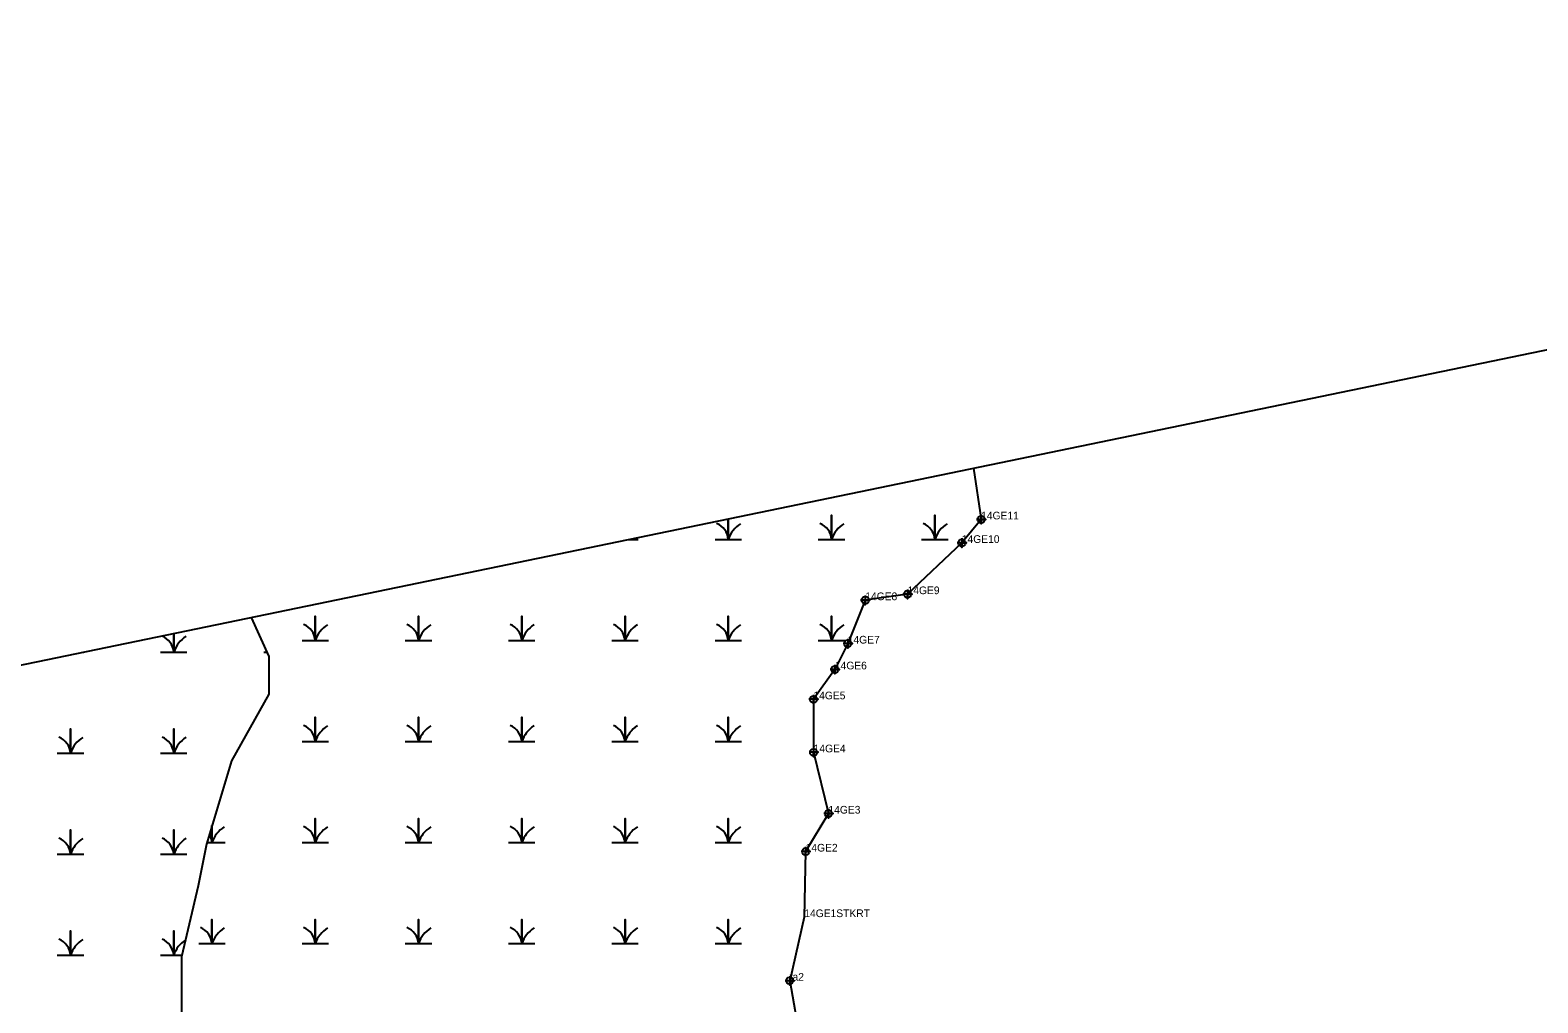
# Model space of a CAD drawing. Extents: x 2071991 to 2268989, y 436479 to 469629.
# Drawn here: x 2259977 to 2260958, y 442009 to 442642 of the extents above; entities that cross this region are included whole.
import ezdxf

# ---------------------------------------------------------------- set-up
doc = ezdxf.new("R2010")
doc.units = 0
for name, color, linetype in [('approx_PSA', 7, 'Continuous'), ('Exist Environmental Wetland Boundary', 7, 'Continuous'), ('Exist Environmental Wetland Boundary Cogo Comment', 7, 'Continuous'), ('Exist Environmental Wetland Boundary Cogo Point CELL', 7, 'Continuous'), ('Exist Hydro Jurisdictional Stream or Body of Water NEU Mitigable', 7, 'Continuous'), ('Exist Hydro Swamp or Marsh', 7, 'Continuous')]:
    doc.layers.add(name, color=color, linetype=linetype)

msp = doc.modelspace()

# ---------------------------------------------------------------- linework, layer by layer
at = {"layer": 'approx_PSA'}
msp.add_line((2259436.93, 442118.42), (2261971.8, 442641.95), dxfattribs=at)
at = {"layer": 'Exist Environmental Wetland Boundary'}
for points in [[(2260590.87, 442356.74), (2260595.94, 442323.44), (2260583.37, 442308.11), (2260548.06, 442274.76), (2260520.53, 442270.84), (2260509.12, 442242.61), (2260500.74, 442225.79), (2260486.8, 442206.3), (2260486.92, 442171.79), (2260496.57, 442131.91), (2260481.73, 442107.18), (2260480.85, 442064.51)], [(2260480.85, 442064.51), (2260471.33, 442023.13), (2260478.24, 441984.37), (2260453.18, 441919.62), (2260429.42, 441892.42), (2260405.4, 441828.34), (2260382.58, 441774.65), (2260378.54, 441677.46), (2260371.11, 441593.52), (2260413.53, 441501.55), (2260451.72, 441470.49), (2260474.35, 441433.89), (2260474.01, 441354.15), (2260435.58, 441283.64), (2260458.13, 441223.04), (2260478.69, 441159.57), (2260523.25, 441103.96), (2260546.39, 441048.63)]]:
    msp.add_lwpolyline(points, dxfattribs=at)
at = {"layer": 'Exist Environmental Wetland Boundary Cogo Point CELL'}
for points in [[(2260595.94, 442326.44), (2260595.94, 442320.44), (2260595.94, 442323.44), (2260598.94, 442323.44), (2260592.94, 442323.44)], [(2260583.37, 442311.11), (2260583.37, 442305.11), (2260583.37, 442308.11), (2260586.37, 442308.11), (2260580.37, 442308.11)], [(2260520.53, 442273.84), (2260520.53, 442267.84), (2260520.53, 442270.84), (2260523.53, 442270.84), (2260517.53, 442270.84)], [(2260548.06, 442277.76), (2260548.06, 442271.76), (2260548.06, 442274.76), (2260551.06, 442274.76), (2260545.06, 442274.76)], [(2260509.12, 442245.61), (2260509.12, 442239.61), (2260509.12, 442242.61), (2260512.12, 442242.61), (2260506.12, 442242.61)], [(2260500.74, 442228.79), (2260500.74, 442222.79), (2260500.74, 442225.79), (2260503.74, 442225.79), (2260497.74, 442225.79)], [(2260486.8, 442209.3), (2260486.8, 442203.3), (2260486.8, 442206.3), (2260489.8, 442206.3), (2260483.8, 442206.3)], [(2260486.92, 442174.79), (2260486.92, 442168.79), (2260486.92, 442171.79), (2260489.92, 442171.79), (2260483.92, 442171.79)], [(2260496.57, 442134.91), (2260496.57, 442128.91), (2260496.57, 442131.91), (2260499.57, 442131.91), (2260493.57, 442131.91)], [(2260481.73, 442110.18), (2260481.73, 442104.18), (2260481.73, 442107.18), (2260484.73, 442107.18), (2260478.73, 442107.18)], [(2260471.33, 442026.13), (2260471.33, 442020.13), (2260471.33, 442023.13), (2260474.33, 442023.13), (2260468.33, 442023.13)]]:
    msp.add_lwpolyline(points, dxfattribs=at)
for centre in [(2260595.94, 442323.44), (2260583.37, 442308.11), (2260548.06, 442274.76), (2260520.53, 442270.84), (2260509.12, 442242.61), (2260500.74, 442225.79), (2260486.8, 442206.3), (2260486.92, 442171.79), (2260496.57, 442131.91), (2260481.73, 442107.18), (2260471.33, 442023.13)]:
    msp.add_circle(centre, 2.34, dxfattribs=at)
at = {"layer": 'Exist Hydro Jurisdictional Stream or Body of Water NEU Mitigable'}
msp.add_lwpolyline([(2260120.87, 442259.67), (2260132.45, 442234.18), (2260132.45, 442209.73), (2260108.02, 442166.28), (2260091.73, 442111.96), (2260086.31, 442084.8), (2260075.45, 442038.62), (2260075.45, 442011.46), (2260075.45, 441973.44), (2260075.45, 441954.42)], dxfattribs=at)
at = {"layer": 'Exist Hydro Swamp or Marsh'}
for p, q in [((2260366.35, 442310.37), (2260372.78, 442310.37)), ((2260011.27, 442237.04), (2260011.88, 442237.04)), ((2260129.08, 442237.04), (2260131.15, 442237.04))]:
    msp.add_line(p, q, dxfattribs=at)
for points in [[(2260422.78, 442310.37), (2260431.38, 442310.37), (2260431.38, 442323.8)], [(2260431.38, 442323.8), (2260431.38, 442310.37), (2260439.98, 442310.37)], [(2260489.98, 442310.37), (2260498.58, 442310.37), (2260498.58, 442326.15), (2260498.58, 442310.37), (2260507.18, 442310.37)], [(2260557.18, 442310.37), (2260565.79, 442310.37), (2260565.79, 442326.15), (2260565.79, 442310.37), (2260574.39, 442310.37)], [(2260153.96, 442244.59), (2260162.57, 442244.59), (2260162.57, 442260.37), (2260162.57, 442244.59), (2260171.17, 442244.59)], [(2260221.17, 442244.59), (2260229.77, 442244.59), (2260229.77, 442260.37), (2260229.77, 442244.59), (2260238.37, 442244.59)], [(2260288.37, 442244.59), (2260296.97, 442244.59), (2260296.97, 442260.37), (2260296.97, 442244.59), (2260305.57, 442244.59)], [(2260355.57, 442244.59), (2260364.18, 442244.59), (2260364.18, 442260.37), (2260364.18, 442244.59), (2260372.78, 442244.59)], [(2260422.78, 442244.59), (2260431.38, 442244.59), (2260431.38, 442260.37), (2260431.38, 442244.59), (2260439.98, 442244.59)], [(2260489.98, 442244.59), (2260498.58, 442244.59), (2260498.58, 442260.37), (2260498.58, 442244.59), (2260507.18, 442244.59)], [(2260061.88, 442237.04), (2260070.48, 442237.04), (2260070.48, 442249.27)], [(2260070.48, 442249.27), (2260070.48, 442237.04), (2260079.08, 442237.04)], [(2259994.68, 442171.26), (2260003.28, 442171.26), (2260003.28, 442187.04), (2260003.28, 442171.26), (2260011.88, 442171.26)], [(2260061.88, 442171.26), (2260070.48, 442171.26), (2260070.48, 442187.04), (2260070.48, 442171.26), (2260079.08, 442171.26)], [(2260153.96, 442178.81), (2260162.57, 442178.81), (2260162.57, 442194.59), (2260162.57, 442178.81), (2260171.17, 442178.81)], [(2260221.17, 442178.81), (2260229.77, 442178.81), (2260229.77, 442194.59), (2260229.77, 442178.81), (2260238.37, 442178.81)], [(2260288.37, 442178.81), (2260296.97, 442178.81), (2260296.97, 442194.59), (2260296.97, 442178.81), (2260305.57, 442178.81)], [(2260355.57, 442178.81), (2260364.18, 442178.81), (2260364.18, 442194.59), (2260364.18, 442178.81), (2260372.78, 442178.81)], [(2260422.78, 442178.81), (2260431.38, 442178.81), (2260431.38, 442194.59), (2260431.38, 442178.81), (2260439.98, 442178.81)], [(2260153.96, 442113.03), (2260162.57, 442113.03), (2260162.57, 442128.81), (2260162.57, 442113.03), (2260171.17, 442113.03)], [(2260221.17, 442113.03), (2260229.77, 442113.03), (2260229.77, 442128.81), (2260229.77, 442113.03), (2260238.37, 442113.03)], [(2260288.37, 442113.03), (2260296.97, 442113.03), (2260296.97, 442128.81), (2260296.97, 442113.03), (2260305.57, 442113.03)], [(2260355.57, 442113.03), (2260364.18, 442113.03), (2260364.18, 442128.81), (2260364.18, 442113.03), (2260372.78, 442113.03)], [(2260422.78, 442113.03), (2260431.38, 442113.03), (2260431.38, 442128.81), (2260431.38, 442113.03), (2260439.98, 442113.03)], [(2259994.68, 442105.48), (2260003.28, 442105.48), (2260003.28, 442121.26), (2260003.28, 442105.48), (2260011.88, 442105.48)], [(2260061.88, 442105.48), (2260070.48, 442105.48), (2260070.48, 442121.26), (2260070.48, 442105.48), (2260079.08, 442105.48)], [(2260092.06, 442113.03), (2260095.36, 442113.03), (2260095.36, 442124.06)], [(2260095.36, 442124.06), (2260095.36, 442113.03), (2260103.96, 442113.03)], [(2260086.76, 442047.25), (2260095.36, 442047.25), (2260095.36, 442063.03), (2260095.36, 442047.25), (2260103.96, 442047.25)], [(2260153.96, 442047.25), (2260162.57, 442047.25), (2260162.57, 442063.03), (2260162.57, 442047.25), (2260171.17, 442047.25)], [(2260221.17, 442047.25), (2260229.77, 442047.25), (2260229.77, 442063.03), (2260229.77, 442047.25), (2260238.37, 442047.25)], [(2260288.37, 442047.25), (2260296.97, 442047.25), (2260296.97, 442063.03), (2260296.97, 442047.25), (2260305.57, 442047.25)], [(2260355.57, 442047.25), (2260364.18, 442047.25), (2260364.18, 442063.03), (2260364.18, 442047.25), (2260372.78, 442047.25)], [(2260422.78, 442047.25), (2260431.38, 442047.25), (2260431.38, 442063.03), (2260431.38, 442047.25), (2260439.98, 442047.25)], [(2259994.68, 442039.69), (2260003.28, 442039.69), (2260003.28, 442055.48), (2260003.28, 442039.69), (2260011.88, 442039.69)], [(2260061.88, 442039.69), (2260070.48, 442039.69), (2260070.48, 442055.48), (2260070.48, 442039.69), (2260075.7, 442039.69)]]:
    msp.add_lwpolyline(points, dxfattribs=at)
for centre, radius, start, end in [((2260419.11, 442309.49), 12.3, 4.14034, 67.53497), ((2260449.62, 442304.31), 19.22, 122.12745, 161.62219), ((2260486.32, 442309.49), 12.3, 4.14034, 67.53497), ((2260516.82, 442304.31), 19.22, 122.12745, 161.62219), ((2260553.52, 442309.49), 12.3, 4.14034, 67.53497), ((2260584.03, 442304.31), 19.22, 122.12745, 161.62219), ((2260150.3, 442243.7), 12.3, 4.14034, 67.53497), ((2260180.81, 442238.53), 19.22, 122.12745, 161.62219), ((2260217.5, 442243.7), 12.3, 4.14034, 67.53497), ((2260248.01, 442238.53), 19.22, 122.12745, 161.62219), ((2260284.71, 442243.7), 12.3, 4.14034, 67.53497), ((2260315.22, 442238.53), 19.22, 122.12745, 161.62219), ((2260351.91, 442243.7), 12.3, 4.14034, 67.53497), ((2260382.42, 442238.53), 19.22, 122.12745, 161.62219), ((2260419.11, 442243.7), 12.3, 4.14034, 67.53497), ((2260449.62, 442238.53), 19.22, 122.12745, 161.62219), ((2260486.32, 442243.7), 12.3, 4.14034, 67.53497), ((2260516.82, 442238.53), 19.22, 122.12745, 161.62219), ((2260058.21, 442236.15), 12.3, 4.14034, 67.53497), ((2260088.72, 442230.98), 19.22, 122.12745, 161.62219), ((2260150.3, 442177.92), 12.3, 4.14034, 67.53497), ((2260180.81, 442172.75), 19.22, 122.12745, 161.62219), ((2260217.5, 442177.92), 12.3, 4.14034, 67.53497), ((2260248.01, 442172.75), 19.22, 122.12745, 161.62219), ((2260284.71, 442177.92), 12.3, 4.14034, 67.53497), ((2260315.22, 442172.75), 19.22, 122.12745, 161.62219), ((2260351.91, 442177.92), 12.3, 4.14034, 67.53497), ((2260382.42, 442172.75), 19.22, 122.12745, 161.62219), ((2260419.11, 442177.92), 12.3, 4.14034, 67.53497), ((2260449.62, 442172.75), 19.22, 122.12745, 161.62219), ((2259991.01, 442170.37), 12.3, 4.14034, 67.53497), ((2260021.52, 442165.2), 19.22, 122.12745, 161.62219), ((2260058.21, 442170.37), 12.3, 4.14034, 67.53497), ((2260088.72, 442165.2), 19.22, 122.12745, 161.62219), ((2260083.1, 442112.14), 12.3, 4.14034, 30.69007), ((2260113.61, 442106.97), 19.22, 122.12745, 161.62219), ((2260150.3, 442112.14), 12.3, 4.14034, 67.53497), ((2260180.81, 442106.97), 19.22, 122.12745, 161.62219), ((2260217.5, 442112.14), 12.3, 4.14034, 67.53497), ((2260248.01, 442106.97), 19.22, 122.12745, 161.62219), ((2260284.71, 442112.14), 12.3, 4.14034, 67.53497), ((2260315.22, 442106.97), 19.22, 122.12745, 161.62219), ((2260351.91, 442112.14), 12.3, 4.14034, 67.53497), ((2260382.42, 442106.97), 19.22, 122.12745, 161.62219), ((2260419.11, 442112.14), 12.3, 4.14034, 67.53497), ((2260449.62, 442106.97), 19.22, 122.12745, 161.62219), ((2260486.32, 442112.14), 12.3, 65.4791, 67.53497), ((2259991.01, 442104.59), 12.3, 4.14034, 67.53497), ((2260021.52, 442099.41), 19.22, 122.12745, 161.62219), ((2260058.21, 442104.59), 12.3, 4.14034, 67.53497), ((2260088.72, 442099.41), 19.22, 122.12745, 161.62219), ((2259991.01, 442038.81), 12.3, 4.14034, 67.53497), ((2260021.52, 442033.63), 19.22, 122.12745, 161.62219), ((2260058.21, 442038.81), 12.3, 4.14034, 67.53497), ((2260088.72, 442033.63), 19.22, 123.78408, 161.62219), ((2260083.1, 442046.36), 12.3, 4.14034, 67.53497), ((2260113.61, 442041.19), 19.22, 122.12745, 161.62219), ((2260150.3, 442046.36), 12.3, 4.14034, 67.53497), ((2260180.81, 442041.19), 19.22, 122.12745, 161.62219), ((2260217.5, 442046.36), 12.3, 4.14034, 67.53497), ((2260248.01, 442041.19), 19.22, 122.12745, 161.62219), ((2260284.71, 442046.36), 12.3, 4.14034, 67.53497), ((2260315.22, 442041.19), 19.22, 122.12745, 161.62219), ((2260351.91, 442046.36), 12.3, 4.14034, 67.53497), ((2260382.42, 442041.19), 19.22, 122.12745, 161.62219), ((2260419.11, 442046.36), 12.3, 4.14034, 67.53497), ((2260449.62, 442041.19), 19.22, 122.12745, 161.62219)]:
    msp.add_arc(centre, radius, start, end, dxfattribs=at)

# ---------------------------------------------------------------- texts
at = {"layer": 'Exist Environmental Wetland Boundary Cogo Comment'}
for s, p in [('14GE11', (2260595.94, 442323.44)), ('14GE10', (2260583.37, 442308.11)), ('14GE8', (2260520.53, 442270.84)), ('14GE9', (2260548.06, 442274.76)), ('14GE7', (2260509.12, 442242.61)), ('14GE6', (2260500.74, 442225.79)), ('14GE5', (2260486.8, 442206.3)), ('14GE4', (2260486.92, 442171.79)), ('14GE3', (2260496.57, 442131.91)), ('14GE2', (2260481.73, 442107.18)), ('14GE1STKRT', (2260480.85, 442064.51)), ('fa2', (2260471.33, 442023.13))]:
    msp.add_text(s, height=5, dxfattribs=at).set_placement(p)

doc.saveas('drawing.dxf')
